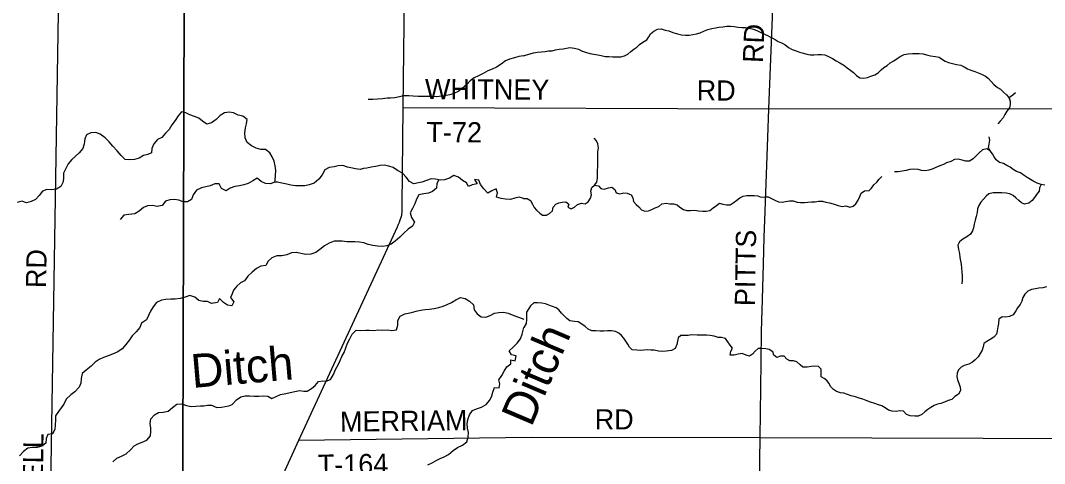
# Model space of a CAD drawing. Extents: x 1857828 to 2277390, y 930619 to 1324581.
# Drawn here: x 2029836 to 2045060, y 1169089 to 1175680 of the extents above; entities that cross this region are included whole.
import ezdxf

# ---------------------------------------------------------------- set-up
doc = ezdxf.new("R2010")
doc.units = 0
for name, color, linetype in [('GM_X_County_Road', 7, 'Continuous'), ('GM_X_Minor_River', 7, 'Continuous'), ('GM_X_Minor_River_Text', 7, 'Continuous'), ('GM_X_Township', 7, 'Continuous'), ('GM_X_Township_Road', 7, 'Continuous'), ('GM_X_Township_Road_Text', 7, 'Continuous')]:
    doc.layers.add(name, color=color, linetype=linetype)

msp = doc.modelspace()

# ---------------------------------------------------------------- linework, layer by layer
at = {"layer": 'GM_X_County_Road'}
msp.add_lwpolyline([(2032427, 1166068), (2032517, 1166270), (2033093, 1167500), (2033974, 1169439), (2035261, 1172223), (2035440, 1172612), (2035457, 1172652), (2035471, 1172680), (2035481, 1172714), (2035492, 1172740), (2035504, 1172782), (2035511, 1172840), (2035512, 1172932), (2035525, 1174386), (2035585, 1179353), (2035534, 1184184), (2035597, 1189529)], dxfattribs=at)
at = {"layer": 'GM_X_Minor_River'}
for points in [[(2037312, 1175153), (2037361, 1175169), (2037412, 1175185), (2037462, 1175197), (2037524, 1175207), (2037581, 1175215), (2037635, 1175220), (2037685, 1175226), (2037739, 1175230), (2037790, 1175244), (2037842, 1175252), (2037902, 1175257), (2037953, 1175269), (2038005, 1175277), (2038071, 1175269), (2038132, 1175251), (2038178, 1175230), (2038236, 1175210), (2038298, 1175190), (2038361, 1175177), (2038419, 1175167), (2038471, 1175157), (2038530, 1175145), (2038582, 1175142), (2038642, 1175138), (2038700, 1175140), (2038763, 1175140), (2038815, 1175152), (2038866, 1175180), (2038908, 1175216), (2038954, 1175255), (2038997, 1175285), (2039037, 1175321), (2039089, 1175359), (2039148, 1175393), (2039178, 1175435), (2039202, 1175483), (2039251, 1175521), (2039307, 1175551), (2039361, 1175555), (2039420, 1175537), (2039476, 1175524), (2039536, 1175502), (2039603, 1175482), (2039663, 1175465), (2039721, 1175461), (2039777, 1175459), (2039832, 1175469), (2039888, 1175483), (2039942, 1175497), (2040003, 1175524), (2040053, 1175546), (2040112, 1175562), (2040170, 1175568), (2040220, 1175578), (2040277, 1175584), (2040335, 1175595), (2040393, 1175597), (2040448, 1175591), (2040506, 1175581), (2040562, 1175574), (2040614, 1175574), (2040669, 1175566), (2040733, 1175552), (2040793, 1175525), (2040845, 1175501), (2040898, 1175477), (2040950, 1175453), (2040996, 1175428), (2041054, 1175396), (2041102, 1175368), (2041151, 1175345), (2041199, 1175321), (2041253, 1175279), (2041309, 1175250), (2041369, 1175230), (2041418, 1175210), (2041476, 1175192), (2041526, 1175177), (2041578, 1175169), (2041637, 1175169), (2041689, 1175175), (2041745, 1175173), (2041796, 1175168), (2041850, 1175146), (2041906, 1175114), (2041964, 1175081), (2042018, 1175051), (2042077, 1175015), (2042125, 1174976), (2042181, 1174938), (2042221, 1174904), (2042265, 1174859), (2042315, 1174825), (2042374, 1174821), (2042426, 1174833), (2042480, 1174849), (2042539, 1174870), (2042585, 1174900), (2042633, 1174944), (2042670, 1174980)], [(2042670, 1174980), (2042720, 1175012), (2042767, 1175050), (2042819, 1175082), (2042869, 1175112), (2042914, 1175142), (2042972, 1175174), (2043032, 1175184), (2043095, 1175191), (2043149, 1175187), (2043199, 1175191), (2043256, 1175183), (2043308, 1175167), (2043366, 1175156), (2043437, 1175144), (2043493, 1175132), (2043541, 1175101), (2043583, 1175073), (2043635, 1175055), (2043692, 1175039), (2043754, 1175024), (2043814, 1175014), (2043868, 1174988), (2043917, 1174962), (2043965, 1174943), (2044023, 1174923), (2044073, 1174899), (2044123, 1174880), (2044184, 1174850), (2044226, 1174816), (2044266, 1174772), (2044308, 1174727), (2044360, 1174685), (2044404, 1174657), (2044450, 1174614), (2044493, 1174572), (2044531, 1174532), (2044551, 1174481), (2044550, 1174431), (2044538, 1174381), (2044500, 1174329), (2044471, 1174281), (2044447, 1174231), (2044403, 1174181), (2044364, 1174143)], [(2037312, 1175153), (2037245, 1175146), (2037181, 1175123), (2037108, 1175102), (2037047, 1175078), (2036982, 1175029), (2036915, 1174986), (2036849, 1174957), (2036782, 1174930), (2036713, 1174891), (2036644, 1174854), (2036581, 1174826), (2036521, 1174783), (2036470, 1174728), (2036404, 1174667), (2036343, 1174621), (2036279, 1174592), (2036218, 1174575), (2036166, 1174562), (2036097, 1174553), (2036025, 1174546), (2035952, 1174549), (2035880, 1174548), (2035749, 1174550), (2035675, 1174553), (2035609, 1174560), (2035530, 1174559), (2035470, 1174542), (2035399, 1174531), (2035335, 1174524), (2035285, 1174523), (2035216, 1174516), (2035144, 1174509), (2035075, 1174506), (2035007, 1174505)], [(2044551, 1174481), (2044539, 1174540), (2044589, 1174574), (2044631, 1174608)], [(2033619, 1173274), (2033621, 1173303), (2033631, 1173448), (2033620, 1173520), (2033605, 1173587), (2033578, 1173651), (2033543, 1173712), (2033479, 1173759), (2033411, 1173762), (2033339, 1173782), (2033269, 1173815), (2033205, 1173864), (2033178, 1173933), (2033173, 1174009), (2033182, 1174081), (2033195, 1174143), (2033208, 1174207), (2033142, 1174254), (2033074, 1174271), (2033002, 1174305), (2032938, 1174314), (2032871, 1174307), (2032807, 1174268), (2032743, 1174208), (2032674, 1174159), (2032604, 1174138), (2032542, 1174181), (2032486, 1174228), (2032424, 1174251), (2032356, 1174278), (2032292, 1174307), (2032228, 1174323), (2032179, 1174259), (2032134, 1174191), (2032087, 1174128), (2032046, 1174060), (2031991, 1174003), (2031938, 1173941), (2031875, 1173908), (2031816, 1173847), (2031787, 1173777), (2031786, 1173711), (2031731, 1173688), (2031664, 1173671), (2031600, 1173633), (2031533, 1173614), (2031461, 1173605), (2031392, 1173614), (2031331, 1173672), (2031271, 1173741), (2031210, 1173810), (2031155, 1173877), (2031095, 1173932), (2031020, 1173988), (2030954, 1174013), (2030883, 1174008), (2030816, 1173979), (2030793, 1173917), (2030784, 1173847), (2030765, 1173775), (2030710, 1173713), (2030651, 1173656), (2030600, 1173610), (2030547, 1173547), (2030477, 1173408), (2030474, 1173343), (2030471, 1173281), (2030434, 1173209), (2030369, 1173170), (2030298, 1173159), (2030226, 1173168), (2030161, 1173139), (2030114, 1173078), (2030057, 1173018), (2029993, 1172987), (2029926, 1172968), (2029858, 1172993), (2029789, 1172970)], [(2038371, 1173229), (2038405, 1173275), (2038415, 1173333), (2038415, 1173395), (2038415, 1173447), (2038418, 1173508), (2038420, 1173570), (2038418, 1173622), (2038420, 1173672), (2038420, 1173726), (2038429, 1173786), (2038421, 1173843), (2038399, 1173891), (2038367, 1173931)], [(2044253, 1173742), (2044227, 1173790), (2044239, 1173842), (2044245, 1173897), (2044239, 1173951)], [(2044253, 1173742), (2044204, 1173772), (2044140, 1173755), (2044090, 1173711), (2044049, 1173669), (2043999, 1173621), (2043944, 1173589), (2043888, 1173587), (2043838, 1173601), (2043776, 1173617), (2043721, 1173612), (2043665, 1173584), (2043604, 1173560), (2043556, 1173538), (2043502, 1173516), (2043445, 1173494), (2043391, 1173466), (2043341, 1173451), (2043286, 1173445), (2043230, 1173449), (2043180, 1173461), (2043113, 1173468), (2043057, 1173464), (2043005, 1173448), (2042942, 1173438), (2042886, 1173428), (2042832, 1173428)], [(2045065, 1173231), (2045011, 1173240), (2044951, 1173262), (2044901, 1173286), (2044854, 1173312), (2044802, 1173345), (2044756, 1173375), (2044702, 1173411), (2044646, 1173432), (2044593, 1173462), (2044551, 1173500), (2044499, 1173524), (2044449, 1173553), (2044391, 1173567), (2044343, 1173605), (2044313, 1173650), (2044287, 1173696), (2044253, 1173742)], [(2037314, 1173034), (2037250, 1173049), (2037184, 1173038), (2037119, 1173015), (2037049, 1173020), (2036983, 1173033), (2036911, 1173053), (2036926, 1173117), (2036906, 1173175), (2036842, 1173148), (2036785, 1173111), (2036723, 1173176), (2036676, 1173239), (2036651, 1173302), (2036587, 1173315), (2036624, 1173248), (2036553, 1173237), (2036495, 1173208), (2036467, 1173264), (2036405, 1173299), (2036346, 1173348), (2036276, 1173373), (2036215, 1173332), (2036142, 1173309), (2036074, 1173304), (2036008, 1173317), (2035941, 1173324), (2035873, 1173301), (2035804, 1173276), (2035752, 1173265), (2035685, 1173248), (2035621, 1173283), (2035570, 1173350), (2035514, 1173409), (2035441, 1173448), (2035377, 1173494), (2035311, 1173513), (2035243, 1173526), (2035182, 1173521), (2035116, 1173510), (2035047, 1173497), (2034985, 1173485), (2034934, 1173476), (2034884, 1173465), (2034818, 1173472), (2034746, 1173487), (2034696, 1173500), (2034627, 1173521), (2034561, 1173516), (2034497, 1173505), (2034424, 1173492), (2034359, 1173457), (2034320, 1173385), (2034269, 1173320), (2034202, 1173258), (2034129, 1173235), (2034062, 1173220), (2033996, 1173219), (2033924, 1173219), (2033855, 1173228), (2033795, 1173243), (2033723, 1173260), (2033655, 1173273)], [(2042052, 1172912), (2042108, 1172922), (2042166, 1172905), (2042215, 1172919), (2042253, 1172953), (2042289, 1173005), (2042316, 1173059), (2042336, 1173111), (2042386, 1173147), (2042451, 1173149), (2042489, 1173187), (2042523, 1173233), (2042568, 1173273), (2042600, 1173317), (2042642, 1173357)], [(2036057, 1173308), (2036057, 1173307), (2036027, 1173255), (2036022, 1173183), (2035963, 1173137), (2035900, 1173112), (2035830, 1173099), (2035759, 1173084), (2035722, 1173022), (2035697, 1172951), (2035666, 1172885), (2035631, 1172817), (2035650, 1172751), (2035693, 1172682), (2035666, 1172618), (2035599, 1172577), (2035534, 1172515), (2035475, 1172456), (2035408, 1172395), (2035347, 1172350), (2035280, 1172328), (2035216, 1172319), (2035145, 1172323), (2035073, 1172334), (2035005, 1172349), (2034941, 1172370), (2034875, 1172381), (2034807, 1172388), (2034756, 1172387), (2034686, 1172388), (2034618, 1172395), (2034568, 1172396), (2034499, 1172395), (2034426, 1172368), (2034354, 1172327), (2034286, 1172273), (2034226, 1172230), (2034153, 1172205), (2034080, 1172198), (2033936, 1172228), (2033864, 1172222), (2033795, 1172196), (2033720, 1172178), (2033646, 1172179), (2033573, 1172150), (2033518, 1172098), (2033481, 1172035), (2033409, 1172026), (2033344, 1171991), (2033281, 1171935), (2033218, 1171878), (2033166, 1171807), (2033108, 1171779), (2033053, 1171728), (2033004, 1171670), (2032983, 1171615), (2032958, 1171561), (2033007, 1171494), (2032976, 1171434), (2032912, 1171445), (2032854, 1171484), (2032793, 1171545), (2032764, 1171485), (2032675, 1171469), (2032617, 1171498), (2032553, 1171501), (2032485, 1171512), (2032427, 1171565), (2032355, 1171590), (2032282, 1171565), (2032210, 1171542), (2032137, 1171533), (2032073, 1171532), (2031999, 1171527), (2031932, 1171518), (2031859, 1171487), (2031810, 1171422), (2031769, 1171356), (2031740, 1171292), (2031709, 1171228), (2031634, 1171177), (2031611, 1171113), (2031556, 1171050), (2031495, 1170991), (2031455, 1170929), (2031404, 1170862), (2031347, 1170796), (2031282, 1170751), (2031205, 1170714), (2031137, 1170689), (2031068, 1170666), (2031005, 1170635), (2030944, 1170596), (2030887, 1170538), (2030812, 1170479), (2030755, 1170426), (2030736, 1170356), (2030731, 1170286), (2030706, 1170224), (2030643, 1170158), (2030582, 1170109)], [(2033655, 1173273), (2033617, 1173273), (2033548, 1173248), (2033478, 1173257), (2033412, 1173285), (2033354, 1173336), (2033289, 1173292), (2033221, 1173257), (2033154, 1173236), (2033092, 1173221), (2033023, 1173208), (2032952, 1173183), (2032893, 1173144), (2032822, 1173181), (2032792, 1173252), (2032724, 1173249), (2032657, 1173222), (2032589, 1173203), (2032526, 1173188), (2032453, 1173155), (2032402, 1173085), (2032377, 1173017), (2032320, 1172980), (2032254, 1172981), (2032192, 1173008), (2032126, 1173019), (2032057, 1173010), (2031991, 1172991), (2031940, 1172927), (2031867, 1172912), (2031797, 1172928), (2031726, 1172921), (2031664, 1172898), (2031599, 1172842), (2031534, 1172803), (2031445, 1172796), (2031373, 1172784), (2031316, 1172718)], [(2037314, 1173034), (2037368, 1173034), (2037419, 1173002), (2037449, 1172949), (2037473, 1172897), (2037509, 1172859), (2037555, 1172813), (2037599, 1172784), (2037655, 1172782), (2037702, 1172810), (2037744, 1172850), (2037754, 1172902), (2037794, 1172946), (2037841, 1172966), (2037891, 1172978), (2037943, 1172982), (2037988, 1172949), (2037973, 1172901), (2038021, 1172877), (2038074, 1172901), (2038118, 1172941), (2038175, 1172961), (2038233, 1172950), (2038277, 1172984), (2038312, 1173036), (2038326, 1173084), (2038316, 1173143), (2038328, 1173193), (2038371, 1173229), (2038427, 1173221), (2038463, 1173178), (2038515, 1173170), (2038578, 1173190), (2038628, 1173198), (2038670, 1173167), (2038690, 1173117), (2038744, 1173099), (2038807, 1173117), (2038857, 1173109), (2038913, 1173084), (2038939, 1173040), (2038951, 1172988), (2038987, 1172943), (2039031, 1172909), (2039067, 1172863), (2039119, 1172845), (2039172, 1172848), (2039222, 1172870), (2039274, 1172892), (2039325, 1172914), (2039373, 1172950), (2039434, 1172960), (2039488, 1172952), (2039542, 1172951), (2039598, 1172939), (2039636, 1172901), (2039691, 1172867), (2039743, 1172854), (2039797, 1172854), (2039856, 1172856), (2039916, 1172848), (2039980, 1172841), (2040030, 1172841), (2040085, 1172855), (2040133, 1172891), (2040182, 1172927), (2040226, 1172963), (2040276, 1172949), (2040330, 1172936), (2040385, 1172938), (2040433, 1172966), (2040487, 1173008), (2040528, 1173040), (2040578, 1173066), (2040634, 1173076), (2040693, 1173077), (2040743, 1173077), (2040799, 1173069), (2040850, 1173049), (2040902, 1173055), (2040952, 1173054), (2041000, 1173034), (2041051, 1173006), (2041105, 1172984), (2041161, 1172979), (2041211, 1172989), (2041268, 1172999), (2041324, 1172995), (2041382, 1172978), (2041433, 1172970), (2041491, 1172972), (2041541, 1172976), (2041597, 1172982), (2041650, 1172983), (2041702, 1172993), (2041758, 1172991), (2041807, 1172977), (2041865, 1172965), (2041919, 1172954), (2041991, 1172928), (2042052, 1172912)], [(2045011, 1173240), (2044985, 1173191), (2044981, 1173141), (2044942, 1173091), (2044910, 1173045), (2044876, 1173003), (2044829, 1172963), (2044765, 1172949), (2044717, 1172966), (2044678, 1173000), (2044634, 1173040), (2044594, 1173075), (2044546, 1173099), (2044492, 1173113), (2044427, 1173117), (2044361, 1173116), (2044297, 1173116), (2044234, 1173100), (2044194, 1173068), (2044152, 1173024), (2044113, 1172978), (2044085, 1172928), (2044065, 1172880), (2044061, 1172824), (2044046, 1172764), (2044030, 1172707), (2044016, 1172651), (2044003, 1172597), (2043987, 1172549), (2043959, 1172501), (2043906, 1172459), (2043844, 1172425), (2043794, 1172389), (2043771, 1172335), (2043783, 1172273), (2043797, 1172211), (2043803, 1172154), (2043811, 1172104), (2043819, 1172054), (2043825, 1171996), (2043832, 1171936), (2043836, 1171881), (2043834, 1171819), (2043830, 1171761)], [(2045089, 1171716), (2045036, 1171704), (2044978, 1171696), (2044924, 1171689), (2044867, 1171679), (2044811, 1171655), (2044766, 1171609), (2044740, 1171557), (2044724, 1171503), (2044700, 1171455), (2044659, 1171405), (2044633, 1171359), (2044595, 1171303), (2044542, 1171275), (2044484, 1171267), (2044430, 1171269), (2044383, 1171235), (2044377, 1171173), (2044367, 1171121), (2044356, 1171065), (2044346, 1171013), (2044306, 1170967), (2044253, 1170935), (2044205, 1170905), (2044159, 1170877), (2044149, 1170825), (2044134, 1170777), (2044104, 1170726), (2044072, 1170674), (2044031, 1170632), (2043987, 1170596), (2043935, 1170565), (2043868, 1170545), (2043822, 1170525), (2043779, 1170483), (2043761, 1170435), (2043757, 1170385), (2043765, 1170332), (2043787, 1170284), (2043805, 1170224), (2043811, 1170174), (2043780, 1170122), (2043726, 1170084), (2043681, 1170044), (2043629, 1170026), (2043571, 1170000), (2043520, 1169982), (2043470, 1169970), (2043418, 1169950), (2043369, 1169925), (2043325, 1169893), (2043283, 1169857), (2043234, 1169819), (2043184, 1169793), (2043132, 1169793), (2043063, 1169797), (2043009, 1169818), (2042963, 1169868), (2042907, 1169874), (2042854, 1169864), (2042796, 1169869), (2042742, 1169885), (2042692, 1169917), (2042641, 1169949), (2042591, 1169964), (2042535, 1169982), (2042471, 1170004), (2042410, 1170025), (2042358, 1170047), (2042306, 1170063), (2042248, 1170081), (2042187, 1170096), (2042131, 1170114), (2042079, 1170134), (2042027, 1170142), (2041966, 1170159)], [(2031209, 1169112), (2031266, 1169169), (2031339, 1169198), (2031406, 1169235), (2031473, 1169292), (2031528, 1169354), (2031579, 1169381), (2031645, 1169406), (2031714, 1169439), (2031767, 1169501), (2031776, 1169567), (2031773, 1169617), (2031764, 1169686), (2031773, 1169752), (2031828, 1169815), (2031887, 1169850), (2031959, 1169851), (2032030, 1169868), (2032095, 1169921), (2032162, 1169973), (2032236, 1169978), (2032304, 1169954), (2032372, 1169937), (2032513, 1169947), (2032564, 1169948), (2032614, 1169958), (2032678, 1169955), (2032756, 1169925), (2032823, 1169928), (2032933, 1169949), (2032984, 1169968), (2033045, 1170036), (2033112, 1170083), (2033177, 1170094), (2033243, 1170095), (2033309, 1170092), (2033378, 1170089), (2033450, 1170096), (2033512, 1170093), (2033574, 1170054), (2033639, 1170087), (2033700, 1170118), (2033780, 1170129), (2033845, 1170146), (2033915, 1170159), (2033982, 1170174), (2034050, 1170165), (2034100, 1170168), (2034163, 1170203), (2034216, 1170249), (2034265, 1170308), (2034330, 1170321), (2034380, 1170316), (2034445, 1170341), (2034490, 1170413), (2034519, 1170487), (2034558, 1170555), (2034589, 1170620), (2034612, 1170682), (2034647, 1170742), (2034674, 1170808), (2034697, 1170878), (2034732, 1170945), (2034769, 1171015), (2034825, 1171071), (2034897, 1171069), (2034969, 1171072), (2035022, 1171074), (2035090, 1171070), (2035154, 1171076), (2035223, 1171075), (2035291, 1171077), (2035359, 1171070), (2035426, 1171079), (2035447, 1171147), (2035446, 1171216), (2035481, 1171281), (2035548, 1171315), (2035598, 1171328), (2035650, 1171337), (2035719, 1171358), (2035782, 1171369), (2035850, 1171380), (2035918, 1171387), (2035987, 1171396), (2036053, 1171411), (2036118, 1171432), (2036181, 1171455), (2036243, 1171483), (2036310, 1171522), (2036379, 1171559), (2036447, 1171542), (2036513, 1171503), (2036571, 1171450), (2036580, 1171377), (2036623, 1171318), (2036683, 1171269), (2036753, 1171264), (2036820, 1171291), (2036885, 1171326), (2036947, 1171337)], [(2041966, 1170159), (2041922, 1170189), (2041880, 1170233), (2041858, 1170280), (2041826, 1170324), (2041786, 1170354), (2041738, 1170378), (2041742, 1170437), (2041742, 1170493), (2041702, 1170531), (2041646, 1170535), (2041590, 1170531), (2041531, 1170524), (2041469, 1170522), (2041427, 1170556), (2041379, 1170600), (2041326, 1170617), (2041274, 1170617), (2041230, 1170643), (2041188, 1170687), (2041136, 1170688), (2041081, 1170666), (2041037, 1170700), (2041019, 1170752), (2040967, 1170785), (2040917, 1170797), (2040858, 1170801), (2040804, 1170799), (2040758, 1170763), (2040721, 1170717), (2040673, 1170687), (2040625, 1170702), (2040563, 1170726), (2040504, 1170714), (2040446, 1170702), (2040388, 1170701), (2040398, 1170761), (2040420, 1170807), (2040388, 1170851), (2040354, 1170899), (2040316, 1170950), (2040260, 1170966), (2040207, 1170962), (2040149, 1170986), (2040087, 1170995), (2040033, 1170997), (2039968, 1170997), (2039896, 1170999), (2039813, 1171002), (2039761, 1170996), (2039705, 1170994), (2039652, 1170996), (2039616, 1170960), (2039604, 1170910), (2039592, 1170858), (2039571, 1170802), (2039515, 1170772), (2039434, 1170762), (2039376, 1170757), (2039320, 1170763), (2039258, 1170773), (2039205, 1170777), (2039155, 1170780), (2039105, 1170774), (2039052, 1170770), (2039000, 1170776), (2038932, 1170778), (2038892, 1170819), (2038864, 1170867), (2038836, 1170909), (2038806, 1170953), (2038772, 1170992), (2038733, 1171026), (2038681, 1171054), (2038623, 1171061), (2038561, 1171061), (2038510, 1171059), (2038452, 1171059), (2038392, 1171061), (2038331, 1171064), (2038277, 1171088), (2038229, 1171130), (2038183, 1171161), (2038125, 1171195), (2038070, 1171201), (2038002, 1171213), (2037960, 1171246), (2037920, 1171286), (2037878, 1171326), (2037840, 1171377), (2037800, 1171407), (2037747, 1171423), (2037693, 1171445), (2037641, 1171464), (2037585, 1171476), (2037522, 1171478), (2037466, 1171478), (2037420, 1171436), (2037391, 1171394), (2037361, 1171340), (2037361, 1171286)], [(2036947, 1171337), (2037015, 1171340), (2037086, 1171325), (2037146, 1171302), (2037318, 1171236)], [(2037361, 1171286), (2037361, 1171232), (2037354, 1171174), (2037319, 1171113)], [(2035890, 1169069), (2035955, 1169098), (2036024, 1169141), (2036074, 1169162), (2036137, 1169187), (2036200, 1169225), (2036267, 1169282), (2036332, 1169329), (2036405, 1169364), (2036470, 1169411), (2036493, 1169481), (2036498, 1169549), (2036481, 1169616), (2036478, 1169678), (2036489, 1169746), (2036512, 1169814), (2036557, 1169878), (2036617, 1169903), (2036688, 1169926), (2036757, 1169967), (2036816, 1170030), (2036843, 1170096), (2036858, 1170150), (2036883, 1170222), (2036951, 1170215), (2036964, 1170275), (2036947, 1170334), (2036992, 1170399), (2037025, 1170465), (2037066, 1170530), (2037127, 1170570), (2037128, 1170634), (2037190, 1170619), (2037203, 1170691), (2037135, 1170704), (2037100, 1170765), (2037163, 1170822), (2037222, 1170881), (2037271, 1170945), (2037292, 1171013), (2037319, 1171113)], [(2030582, 1170109), (2030514, 1170046), (2030479, 1169974), (2030440, 1169917), (2030399, 1169865), (2030356, 1169801), (2030357, 1169733), (2030352, 1169663), (2030347, 1169595), (2030312, 1169529), (2030244, 1169520), (2030217, 1169462), (2030212, 1169392), (2030155, 1169345), (2030084, 1169330), (2030016, 1169327), (2029947, 1169316), (2029882, 1169267), (2029821, 1169205)]]:
    msp.add_lwpolyline(points, dxfattribs=at)
at = {"layer": 'GM_X_Township'}
msp.add_lwpolyline([(2026607, 1193454), (2030478, 1193460), (2032345, 1193489), (2032348, 1192998), (2032309, 1188668), (2032281, 1179371), (2032243, 1167507), (2032206, 1165870), (2028230, 1165900)], dxfattribs=at)
msp.add_lwpolyline([(2032206, 1165870), (2032243, 1167507), (2032281, 1179371), (2032309, 1188668), (2032348, 1192998), (2035009, 1192996), (2046211, 1193046), (2052905, 1193059), (2052996, 1193078), (2056703, 1193080), (2060043, 1193100), (2060012, 1189567), (2060011, 1189355), (2059891, 1179593), (2059723, 1165822), (2056293, 1165821), (2053083, 1165829), (2051080, 1165830), (2046516, 1165826), (2039516, 1165835), (2032339, 1165871)], close=True, dxfattribs=at)
at = {"layer": 'GM_X_Township_Road'}
for points in [[(2030266, 1167521), (2030459, 1179472)], [(2040960, 1174364), (2041158, 1179325)], [(2035525, 1174386), (2040960, 1174364), (2045875, 1174371)], [(2040834, 1169478), (2040845, 1170212), (2040848, 1170605), (2040854, 1171054), (2040868, 1171536), (2040881, 1172055), (2040891, 1172456), (2040902, 1172711), (2040919, 1173116), (2040948, 1173939), (2040960, 1174364)], [(2033974, 1169439), (2037428, 1169481), (2040834, 1169478)], [(2039516, 1165835), (2039535, 1165898), (2039597, 1166007), (2040205, 1167120), (2040685, 1167992), (2040747, 1168098), (2040773, 1168146), (2040787, 1168180), (2040799, 1168208), (2040807, 1168235), (2040814, 1168293), (2040818, 1168461), (2040834, 1169478)], [(2040834, 1169478), (2045806, 1169462)]]:
    msp.add_lwpolyline(points, dxfattribs=at)

# ---------------------------------------------------------------- texts
at = {"layer": 'GM_X_Minor_River_Text'}
for height, rotation, p in [(500.3, 66.9079, (2037430, 1169618)), (500.2, 4.9066, (2032392, 1170213))]:
    msp.add_text('Ditch', height=height, rotation=rotation, dxfattribs=at).set_placement(p)
at = {"layer": 'GM_X_Township_Road_Text'}
for s, rotation, p in [('RD', 87.5314, (2040873, 1175044)), ('WHITNEY', 359.7056, (2035848, 1174510)), ('RD', 359.5064, (2039888, 1174492)), ('T-72', 359.6465, (2035871, 1173871)), ('PITTS', 88.9687, (2040754, 1171428)), ('RD', 89.0127, (2030216, 1171697)), ('MERRIAM', 0.7199, (2034588, 1169561)), ('RD', 0, (2038373, 1169596)), ('ROWELL', 89.1749, (2030155, 1167842)), ('T-164', 0.8421, (2034258, 1168921))]:
    msp.add_text(s, height=300, rotation=rotation, dxfattribs=at).set_placement(p)

doc.saveas('drawing.dxf')
